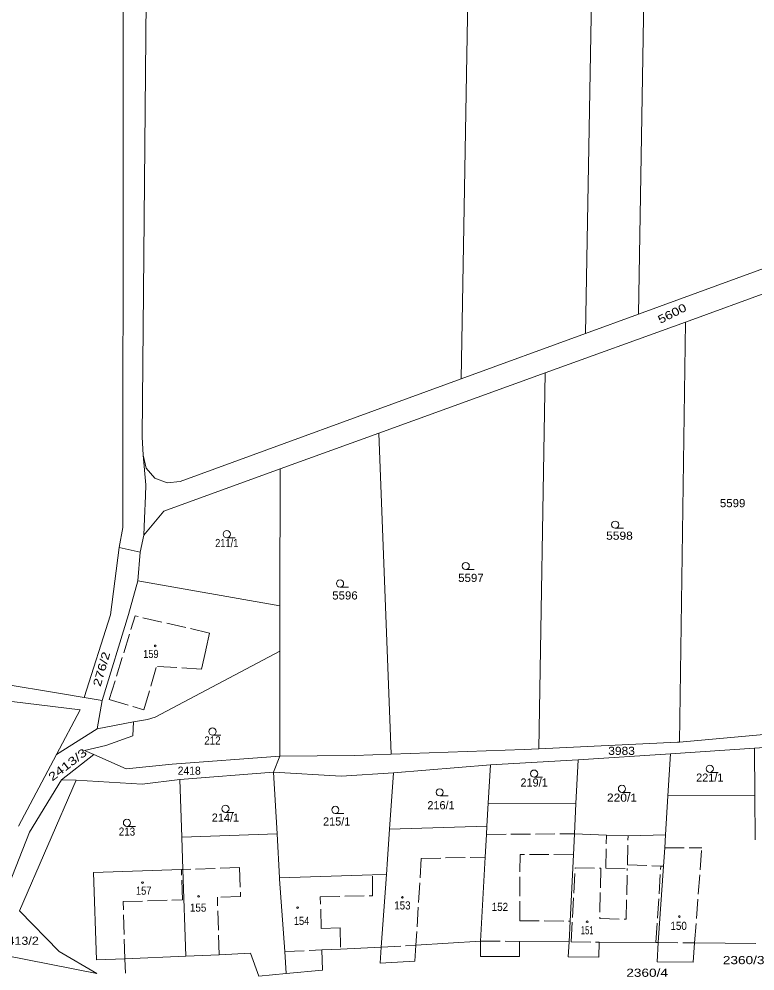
# Model space of a CAD drawing. Extents: x -590528 to -586543, y -1119609 to -1116685.
# Drawn here: x -588918.2 to -588764.7, y -1118121.8 to -1117923.1 of the extents above; entities that cross this region are included whole.
import ezdxf
from ezdxf.enums import TextEntityAlignment as Align

# ---------------------------------------------------------------- set-up
doc = ezdxf.new("R2010")
doc.units = 0
doc.header["$LTSCALE"] = 0.68
doc.linetypes.add('LONG_DASHED', pattern=[7.5, 6, -1.5])
for name, color, linetype, lineweight in [('1', 7, 'Continuous', 13), ('2', 7, 'LONG_DASHED', 13), ('3', 7, 'Continuous', 13), ('6', 7, 'Continuous', 13)]:
    doc.layers.add(name, color=color, linetype=linetype, lineweight=lineweight)

msp = doc.modelspace()

# ---------------------------------------------------------------- linework, layer by layer
at = {"layer": '1'}
for p, q in [((-588789.02, -1117984.7), (-588785.91, -1117804.73)), ((-588826, -1117998.2), (-588822.81, -1117813.26)), ((-588800.03, -1117988.72), (-588797.05, -1117815.84)), ((-588760.63, -1117974.34), (-588789.02, -1117984.7)), ((-588789.02, -1117984.7), (-588800.03, -1117988.72)), ((-588800.03, -1117988.72), (-588826, -1117998.2)), ((-588843.2, -1118009.54), (-588863.78, -1118017)), ((-588888.04, -1118025.8), (-588863.78, -1118017)), ((-588892.19, -1118030.82), (-588888.04, -1118025.8)), ((-588892.95, -1118034.36), (-588892.19, -1118030.82)), ((-588897.36, -1118033.39), (-588892.95, -1118034.36)), ((-588893.46, -1118040.37), (-588863.81, -1118045.57)), ((-588900.86, -1118065.35), (-588895.42, -1118047.37)), ((-588889.87, -1118068.8), (-588863.82, -1118055.06)), ((-588863.84, -1118076.94), (-588863.82, -1118055.06)), ((-588909.17, -1118063.97), (-588938.59, -1118059.07)), ((-588905.49, -1118067.28), (-588934.47, -1118063.73)), ((-588904.62, -1118064.73), (-588900.86, -1118065.35)), ((-588900.86, -1118065.35), (-588901.97, -1118071.23)), ((-588894.5, -1118072.7), (-588894.35, -1118069.82)), ((-588891.43, -1118069.27), (-588889.87, -1118068.8)), ((-588901.97, -1118071.23), (-588910.42, -1118076.58)), ((-588900.15, -1118074.7), (-588894.5, -1118072.7)), ((-588780.43, -1118074), (-588761.3, -1118072.29)), ((-588900.15, -1118074.7), (-588904.56, -1118075.79)), ((-588840.63, -1118076.51), (-588812.85, -1118075.53)), ((-588812.85, -1118075.53), (-588809.79, -1118075.39)), ((-588809.79, -1118075.39), (-588780.83, -1118074.04)), ((-588780.83, -1118074.04), (-588780.43, -1118074)), ((-588764.74, -1118085.12), (-588764.82, -1118075.28)), ((-588909.4, -1118081.92), (-588902.66, -1118076.63)), ((-588863.84, -1118076.94), (-588886.31, -1118078.62)), ((-588865.13, -1118080.26), (-588863.84, -1118076.94)), ((-588863.84, -1118076.94), (-588848.27, -1118076.78)), ((-588848.27, -1118076.78), (-588840.63, -1118076.51)), ((-588819.91, -1118078.73), (-588801.58, -1118077.73)), ((-588801.58, -1118077.73), (-588802.04, -1118086.85)), ((-588801.58, -1118077.73), (-588782.33, -1118076.48)), ((-588886.31, -1118078.62), (-588895.89, -1118079.61)), ((-588819.91, -1118078.73), (-588820.35, -1118086.79)), ((-588865.13, -1118080.26), (-588864.41, -1118093.18)), ((-588906.34, -1118081.97), (-588918.11, -1118109.25)), ((-588906.34, -1118081.97), (-588909.4, -1118081.92)), ((-588906.34, -1118081.97), (-588892.55, -1118082.83)), ((-588782.86, -1118085.25), (-588764.74, -1118085.12)), ((-588764.67, -1118094.4), (-588764.74, -1118085.12)), ((-588840.94, -1118092.21), (-588820.61, -1118091.57)), ((-588884.28, -1118093.87), (-588864.41, -1118093.18)), ((-588863.91, -1118102.35), (-588864.41, -1118093.18)), ((-588820.71, -1118093.3), (-588820.97, -1118098.02)), ((-588795.69, -1118093.45), (-588802.36, -1118093.14)), ((-588791.19, -1118093.55), (-588795.69, -1118093.45)), ((-588791.19, -1118093.55), (-588783.35, -1118093.39)), ((-588803.28, -1118111.42), (-588802.58, -1118097.53)), ((-588841.38, -1118098.45), (-588841.6, -1118101.63)), ((-588884.35, -1118100.61), (-588902.68, -1118101.22)), ((-588902.08, -1118119.48), (-588902.68, -1118101.22)), ((-588884.05, -1118100.6), (-588884.35, -1118100.61)), ((-588884.05, -1118100.6), (-588883.44, -1118118.73)), ((-588841.6, -1118101.63), (-588842.67, -1118116.84)), ((-588783.75, -1118099.91), (-588784.87, -1118115.88)), ((-588863.91, -1118102.35), (-588863.89, -1118102.64)), ((-588803.28, -1118111.42), (-588803.49, -1118115.71)), ((-588835.44, -1118116.39), (-588821.93, -1118115.54)), ((-588855.05, -1118117.4), (-588851.19, -1118117.23)), ((-588854.92, -1118121.59), (-588855.05, -1118117.4)), ((-588851.19, -1118117.23), (-588842.67, -1118116.84)), ((-588842.67, -1118116.84), (-588842.92, -1118120.18)), ((-588835.44, -1118116.39), (-588835.65, -1118119.73)), ((-588813.84, -1118118.75), (-588813.82, -1118115.61)), ((-588813.82, -1118115.61), (-588803.49, -1118115.71)), ((-588797.2, -1118115.77), (-588797.27, -1118118.91)), ((-588797.2, -1118115.77), (-588785.35, -1118115.88)), ((-588785.35, -1118115.88), (-588784.87, -1118115.88)), ((-588777.61, -1118119.92), (-588777.31, -1118115.95)), ((-588777.31, -1118115.95), (-588764.5, -1118116.07)), ((-588921.38, -1118118.49), (-588901.98, -1118122.35)), ((-588896.14, -1118119.24), (-588902.08, -1118119.48)), ((-588883.44, -1118118.73), (-588896.14, -1118119.24)), ((-588896.04, -1118122.23), (-588896.14, -1118119.24)), ((-588835.65, -1118119.73), (-588842.92, -1118120.18)), ((-588862.48, -1118122.31), (-588854.92, -1118121.59))]:
    msp.add_line(p, q, dxfattribs=at)
for points in [[(-588892.52, -1118010.27), (-588891.23, -1117865.97), (-588889.63, -1117828.79), (-588885.3, -1117821.98), (-588822.39, -1117788.91)], [(-588895.38, -1117847.24), (-588896.51, -1117887.9), (-588896.48, -1117949.18)], [(-588896.48, -1117949.18), (-588896.56, -1118029.25), (-588897.36, -1118033.39), (-588899.14, -1118047.42)], [(-588760.88, -1117979.71), (-588779.21, -1117986.35), (-588780.43, -1118074)], [(-588779.21, -1117986.35), (-588808.44, -1117996.95), (-588809.79, -1118075.39)], [(-588826, -1117998.2), (-588884.59, -1118019.59), (-588887.31, -1118019.89), (-588889.89, -1118018.89)], [(-588808.44, -1117996.95), (-588843.2, -1118009.54), (-588840.63, -1118076.51)], [(-588889.89, -1118018.89), (-588891.71, -1118016.81), (-588892.36, -1118014.14), (-588892.52, -1118010.27)], [(-588892.19, -1118030.82), (-588892.08, -1118027.34), (-588891.82, -1118022.64), (-588891.8, -1118020.29), (-588892.36, -1118014.14)], [(-588863.82, -1118055.06), (-588863.81, -1118045.57), (-588863.78, -1118017)], [(-588895.42, -1118047.37), (-588893.46, -1118040.37), (-588892.95, -1118034.36)], [(-588899.14, -1118047.42), (-588904.62, -1118064.73), (-588909.17, -1118063.97)], [(-588918.36, -1118091.58), (-588910.42, -1118076.58), (-588905.49, -1118067.28)], [(-588901.97, -1118071.23), (-588894.35, -1118069.82), (-588891.43, -1118069.27)], [(-588904.56, -1118075.79), (-588902.66, -1118076.63), (-588895.89, -1118079.61)], [(-588764.82, -1118075.28), (-588782.33, -1118076.48), (-588782.86, -1118085.25), (-588783.35, -1118093.39)], [(-588750.27, -1118083.86), (-588750.41, -1118074.32), (-588764.82, -1118075.28)], [(-588865.13, -1118080.26), (-588851.01, -1118081.12), (-588840.11, -1118080.43), (-588819.91, -1118078.73)], [(-588892.55, -1118082.83), (-588884.68, -1118081.81), (-588865.13, -1118080.26)], [(-588884.68, -1118081.81), (-588884.28, -1118093.87), (-588884.05, -1118100.6)], [(-588840.11, -1118080.43), (-588840.94, -1118092.21), (-588841.38, -1118098.45)], [(-588909.4, -1118081.92), (-588916.04, -1118092.82), (-588920.34, -1118103.8)], [(-588820.35, -1118086.79), (-588820.61, -1118091.57), (-588820.71, -1118093.3)], [(-588820.35, -1118086.79), (-588802.04, -1118086.85), (-588802.36, -1118093.14), (-588802.58, -1118097.53)], [(-588783.35, -1118093.39), (-588783.52, -1118096.11), (-588783.75, -1118099.91)], [(-588820.97, -1118098.02), (-588821.93, -1118115.54), (-588821.97, -1118118.8), (-588813.84, -1118118.75)], [(-588863.91, -1118102.35), (-588844.49, -1118101.72), (-588841.6, -1118101.63)], [(-588863.89, -1118102.64), (-588862.81, -1118117.75), (-588862.48, -1118122.31), (-588868.2, -1118122.84), (-588869.94, -1118118.08)], [(-588918.11, -1118109.25), (-588909.85, -1118117.75), (-588901.98, -1118122.35)], [(-588803.49, -1118115.71), (-588803.65, -1118118.81), (-588797.27, -1118118.91)], [(-588784.87, -1118115.88), (-588785.14, -1118119.9), (-588777.61, -1118119.92)], [(-588883.44, -1118118.73), (-588876.51, -1118118.4), (-588869.94, -1118118.08)]]:
    msp.add_lwpolyline(points, dxfattribs=at)
at = {"layer": '2'}
for p, q in [((-588899.4, -1118065.13), (-588894.04, -1118047.68)), ((-588878.47, -1118051.25), (-588894.04, -1118047.68)), ((-588879.28, -1118054.77), (-588878.47, -1118051.25)), ((-588880.2, -1118058.78), (-588879.28, -1118054.77)), ((-588880.2, -1118058.78), (-588889.55, -1118058.21)), ((-588820.71, -1118093.3), (-588802.36, -1118093.14)), ((-588795.84, -1118100.35), (-588795.69, -1118093.45)), ((-588791.32, -1118099.61), (-588791.19, -1118093.55)), ((-588813.79, -1118111.3), (-588813.7, -1118097.46)), ((-588802.58, -1118097.53), (-588813.7, -1118097.46)), ((-588783.52, -1118096.11), (-588775.81, -1118096.08)), ((-588834.33, -1118098.3), (-588835.44, -1118116.39)), ((-588834.33, -1118098.3), (-588820.97, -1118098.02)), ((-588884.14, -1118106.91), (-588884.35, -1118100.61)), ((-588872.22, -1118100.21), (-588884.05, -1118100.6)), ((-588872.22, -1118100.21), (-588872.04, -1118106.23)), ((-588803.04, -1118115.71), (-588802.23, -1118100.29)), ((-588802.23, -1118100.29), (-588796.86, -1118100.34)), ((-588796.86, -1118100.34), (-588797.09, -1118110.87)), ((-588795.84, -1118100.35), (-588791.34, -1118100.39)), ((-588791.57, -1118110.99), (-588791.34, -1118100.39)), ((-588785.35, -1118115.88), (-588784.34, -1118099.89)), ((-588896.53, -1118107.32), (-588884.14, -1118106.91)), ((-588896.14, -1118119.24), (-588896.53, -1118107.32)), ((-588872.04, -1118106.23), (-588876.86, -1118106.38)), ((-588876.51, -1118118.4), (-588876.86, -1118106.38)), ((-588855.18, -1118112.94), (-588855.38, -1118106.31)), ((-588813.79, -1118111.3), (-588803.28, -1118111.42)), ((-588797.09, -1118110.87), (-588791.57, -1118110.99)), ((-588855.18, -1118112.94), (-588851.24, -1118112.76)), ((-588851.24, -1118112.76), (-588851.19, -1118117.23)), ((-588821.93, -1118115.54), (-588813.82, -1118115.61)), ((-588862.81, -1118117.75), (-588855.05, -1118117.4)), ((-588842.67, -1118116.84), (-588835.44, -1118116.39)), ((-588803.04, -1118115.71), (-588797.2, -1118115.77))]:
    msp.add_line(p, q, dxfattribs=at)
for points in [[(-588899.4, -1118065.13), (-588892.2, -1118067.25), (-588889.55, -1118058.21)], [(-588784.87, -1118115.88), (-588777.31, -1118115.95), (-588775.81, -1118096.08)], [(-588791.32, -1118099.61), (-588784.34, -1118099.89), (-588783.75, -1118099.91)], [(-588855.38, -1118106.31), (-588844.49, -1118106.08), (-588844.49, -1118101.72)]]:
    msp.add_lwpolyline(points, dxfattribs=at)
at = {"layer": '6'}
for p, q in [((-588793.86, -1118029.38), (-588792.11, -1118029.38)), ((-588874.9, -1118031.36), (-588873.15, -1118031.36)), ((-588825.05, -1118038.01), (-588823.3, -1118038.01)), ((-588851.27, -1118041.66), (-588849.52, -1118041.66)), ((-588877.88, -1118072.57), (-588876.13, -1118072.57)), ((-588810.78, -1118081.35), (-588809.03, -1118081.35)), ((-588774.13, -1118080.33), (-588772.38, -1118080.33)), ((-588830.48, -1118085.25), (-588828.73, -1118085.25)), ((-588792.45, -1118084.51), (-588790.7, -1118084.51)), ((-588875.18, -1118088.68), (-588873.43, -1118088.68)), ((-588852.25, -1118088.92), (-588850.5, -1118088.92)), ((-588895.72, -1118091.6), (-588893.97, -1118091.6))]:
    msp.add_line(p, q, dxfattribs=at)
for centre, radius in [((-588793.86, -1118028.63), 0.75), ((-588874.9, -1118030.61), 0.75), ((-588825.05, -1118037.26), 0.75), ((-588851.27, -1118040.91), 0.75), ((-588889.8202, -1118053.9404), 0.175), ((-588877.88, -1118071.82), 0.75), ((-588774.13, -1118079.58), 0.75), ((-588810.78, -1118080.6), 0.75), ((-588830.48, -1118084.5), 0.75), ((-588792.45, -1118083.76), 0.75), ((-588875.18, -1118087.93), 0.75), ((-588852.25, -1118088.17), 0.75), ((-588895.72, -1118090.85), 0.75), ((-588892.4802, -1118103.3504), 0.175), ((-588880.7902, -1118106.2204), 0.175), ((-588838.2602, -1118106.4204), 0.175), ((-588860.1302, -1118108.5704), 0.175), ((-588799.7102, -1118111.5104), 0.175), ((-588780.4702, -1118110.4304), 0.175)]:
    msp.add_circle(centre, radius, dxfattribs=at)

# ---------------------------------------------------------------- texts
at = {"layer": '3', "width": 1.25}
msp.add_text('5600', height=1.7, rotation=26.814, dxfattribs=at).set_placement((-588784.428, -1117986.733))
at = {"layer": '3'}
for s, width, p in [('5599', 1.05, (-588772.013, -1118024.98)), ('5598', 1.1, (-588795.753, -1118031.78)), ('5597', 1.05, (-588826.613, -1118040.59)), ('5596', 1.05, (-588852.893, -1118044.25))]:
    msp.add_text(s, height=1.7, dxfattribs=dict(at, width=width)).set_placement(p)
for s, width, p in [('211/1', 0.85, (-588874.9005, -1118033.31)), ('159', 0.85, (-588890.7305, -1118056.47)), ('212', 0.9, (-588877.88, -1118074.52)), ('3983', 1.1, (-588792.53, -1118076.69)), ('2418', 0.95, (-588882.73, -1118080.83)), ('220/1', 1.1, (-588792.45, -1118086.46)), ('213', 0.9, (-588895.7205, -1118093.55)), ('157', 0.85, (-588892.2305, -1118105.88)), ('153', 0.9, (-588838.26, -1118108.95)), ('152', 0.9, (-588817.9105, -1118109.26)), ('155', 0.9, (-588880.8705, -1118109.42)), ('154', 0.85, (-588859.2905, -1118112.18)), ('150', 0.9, (-588780.6205, -1118113.22)), ('151', 0.7, (-588799.7105, -1118114.14)), ('2413/2', 1.15, (-588918.1105, -1118116.33)), ('2360/3', 1.25, (-588767.0605, -1118120.37)), ('2360/4', 1.25, (-588787.2015, -1118123.01))]:
    msp.add_text(s, height=1.7, dxfattribs=dict(at, width=width)).set_placement(p, align=Align.CENTER)
for s, rotation, width, p in [('276/2', 73.969, 1.3, (-588900.213, -1118059.0062)), ('2413/3', 37.586, 1.35, (-588907.6015, -1118079.4008))]:
    msp.add_text(s, height=1.7, rotation=rotation, dxfattribs=dict(at, width=width)).set_placement(p, align=Align.CENTER)
for s, p in [('219/1', (-588810.7805, -1118083.3)), ('221/1', (-588774.13, -1118082.28)), ('216/1', (-588830.2005, -1118088.04)), ('214/1', (-588875.1805, -1118090.63)), ('215/1', (-588851.9705, -1118091.43))]:
    msp.add_text(s, height=1.7, dxfattribs=at).set_placement(p, align=Align.CENTER)

doc.saveas('drawing.dxf')
